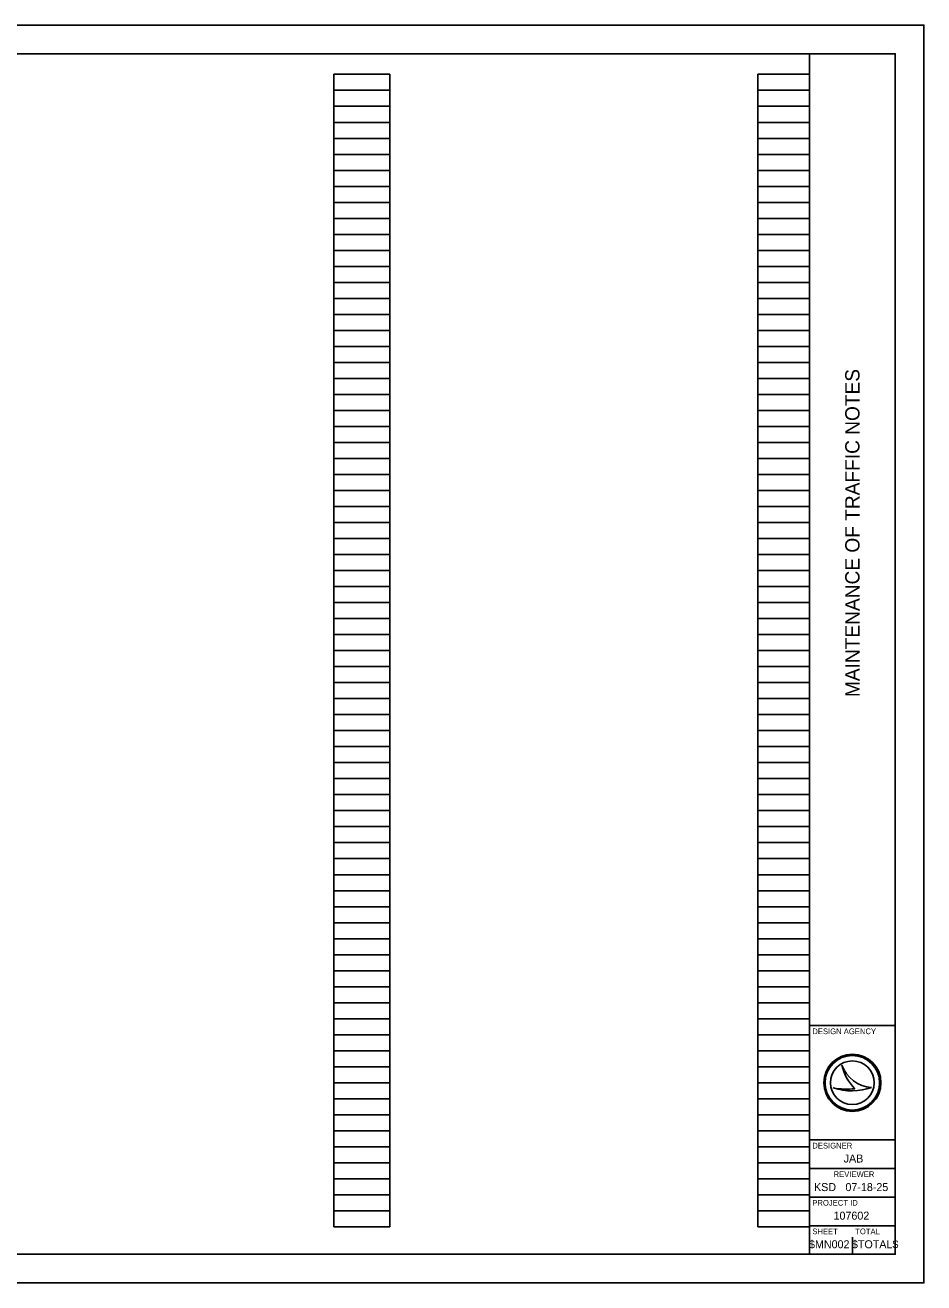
# Model space of a CAD drawing. Extents: x 0 to 34, y 0 to 22.
# Drawn here: x 18.29 to 34, y 0 to 22 of the extents above; entities that cross this region are included whole.
import ezdxf

# ---------------------------------------------------------------- set-up
doc = ezdxf.new("R2010")
doc.units = 0
for name, color, linetype in [('SH_Border', 7, 'Continuous'), ('SH_Cut_Line', 7, 'Continuous'), ('SH_Data', 7, 'Continuous')]:
    doc.layers.add(name, color=color, linetype=linetype)

msp = doc.modelspace()

# ---------------------------------------------------------------- linework, layer by layer
at = {"layer": 'SH_Border'}
for p, q in [((32, 0.5), (32, 21.5)), ((32, 4.5), (33.5, 4.5)), ((32, 2.5), (33.5, 2.5)), ((32, 2), (33.5, 2)), ((32, 1.5), (33.5, 1.5)), ((32, 1), (33.5, 1))]:
    msp.add_line(p, q, dxfattribs=at)
msp.add_lwpolyline([(1.5, 21.5), (33.5, 21.5), (33.5, 0.5), (1.5, 0.5)], close=True, dxfattribs=at)
at = {"layer": 'SH_Cut_Line'}
msp.add_lwpolyline([(0, 0), (34, 0), (34, 22), (0, 22)], close=True, dxfattribs=at)
at = {"layer": 'SH_Data'}
for p, q in [((23.68, 0.98), (23.68, 21.14)), ((23.68, 21.14), (24.66, 21.14)), ((24.66, 0.98), (24.66, 21.14)), ((31.1, 0.98), (31.1, 21.14)), ((31.1, 21.14), (32, 21.14)), ((32, 0.98), (32, 21.14)), ((23.68, 20.86), (24.66, 20.86)), ((31.1, 20.86), (32, 20.86)), ((23.68, 20.58), (24.66, 20.58)), ((31.1, 20.58), (32, 20.58)), ((23.68, 20.3), (24.66, 20.3)), ((31.1, 20.3), (32, 20.3)), ((23.68, 20.02), (24.66, 20.02)), ((31.1, 20.02), (32, 20.02)), ((23.68, 19.74), (24.66, 19.74)), ((31.1, 19.74), (32, 19.74)), ((23.68, 19.46), (24.66, 19.46)), ((31.1, 19.46), (32, 19.46)), ((23.68, 19.18), (24.66, 19.18)), ((31.1, 19.18), (32, 19.18)), ((23.68, 18.9), (24.66, 18.9)), ((31.1, 18.9), (32, 18.9)), ((23.68, 18.62), (24.66, 18.62)), ((31.1, 18.62), (32, 18.62)), ((23.68, 18.34), (24.66, 18.34)), ((31.1, 18.34), (32, 18.34)), ((23.68, 18.06), (24.66, 18.06)), ((31.1, 18.06), (32, 18.06)), ((23.68, 17.78), (24.66, 17.78)), ((31.1, 17.78), (32, 17.78)), ((23.68, 17.5), (24.66, 17.5)), ((31.1, 17.5), (32, 17.5)), ((23.68, 17.22), (24.66, 17.22)), ((31.1, 17.22), (32, 17.22)), ((23.68, 16.94), (24.66, 16.94)), ((31.1, 16.94), (32, 16.94)), ((23.68, 16.66), (24.66, 16.66)), ((31.1, 16.66), (32, 16.66)), ((23.68, 16.38), (24.66, 16.38)), ((31.1, 16.38), (32, 16.38)), ((23.68, 16.1), (24.66, 16.1)), ((31.1, 16.1), (32, 16.1)), ((23.68, 15.82), (24.66, 15.82)), ((31.1, 15.82), (32, 15.82)), ((23.68, 15.54), (24.66, 15.54)), ((31.1, 15.54), (32, 15.54)), ((23.68, 15.26), (24.66, 15.26)), ((31.1, 15.26), (32, 15.26)), ((23.68, 14.98), (24.66, 14.98)), ((31.1, 14.98), (32, 14.98)), ((23.68, 14.7), (24.66, 14.7)), ((31.1, 14.7), (32, 14.7)), ((23.68, 14.42), (24.66, 14.42)), ((31.1, 14.42), (32, 14.42)), ((23.68, 14.14), (24.66, 14.14)), ((31.1, 14.14), (32, 14.14)), ((23.68, 13.86), (24.66, 13.86)), ((31.1, 13.86), (32, 13.86)), ((23.68, 13.58), (24.66, 13.58)), ((31.1, 13.58), (32, 13.58)), ((23.68, 13.3), (24.66, 13.3)), ((31.1, 13.3), (32, 13.3)), ((23.68, 13.02), (24.66, 13.02)), ((31.1, 13.02), (32, 13.02)), ((23.68, 12.74), (24.66, 12.74)), ((31.1, 12.74), (32, 12.74)), ((23.68, 12.46), (24.66, 12.46)), ((31.1, 12.46), (32, 12.46)), ((23.68, 12.18), (24.66, 12.18)), ((31.1, 12.18), (32, 12.18)), ((23.68, 11.9), (24.66, 11.9)), ((31.1, 11.9), (32, 11.9)), ((23.68, 11.62), (24.66, 11.62)), ((31.1, 11.62), (32, 11.62)), ((23.68, 11.34), (24.66, 11.34)), ((31.1, 11.34), (32, 11.34)), ((23.68, 11.06), (24.66, 11.06)), ((31.1, 11.06), (32, 11.06)), ((23.68, 10.78), (24.66, 10.78)), ((31.1, 10.78), (32, 10.78)), ((23.68, 10.5), (24.66, 10.5)), ((31.1, 10.5), (32, 10.5)), ((23.68, 10.22), (24.66, 10.22)), ((31.1, 10.22), (32, 10.22)), ((23.68, 9.94), (24.66, 9.94)), ((31.1, 9.94), (32, 9.94)), ((23.68, 9.66), (24.66, 9.66)), ((31.1, 9.66), (32, 9.66)), ((23.68, 9.38), (24.66, 9.38)), ((31.1, 9.38), (32, 9.38)), ((23.68, 9.1), (24.66, 9.1)), ((31.1, 9.1), (32, 9.1)), ((23.68, 8.82), (24.66, 8.82)), ((31.1, 8.82), (32, 8.82)), ((23.68, 8.54), (24.66, 8.54)), ((31.1, 8.54), (32, 8.54)), ((23.68, 8.26), (24.66, 8.26)), ((31.1, 8.26), (32, 8.26)), ((23.68, 7.98), (24.66, 7.98)), ((31.1, 7.98), (32, 7.98)), ((23.68, 7.7), (24.66, 7.7)), ((31.1, 7.7), (32, 7.7)), ((23.68, 7.42), (24.66, 7.42)), ((31.1, 7.42), (32, 7.42)), ((23.68, 7.14), (24.66, 7.14)), ((31.1, 7.14), (32, 7.14)), ((23.68, 6.86), (24.66, 6.86)), ((31.1, 6.86), (32, 6.86)), ((23.68, 6.58), (24.66, 6.58)), ((31.1, 6.58), (32, 6.58)), ((23.68, 6.3), (24.66, 6.3)), ((31.1, 6.3), (32, 6.3)), ((23.68, 6.02), (24.66, 6.02)), ((31.1, 6.02), (32, 6.02)), ((23.68, 5.74), (24.66, 5.74)), ((31.1, 5.74), (32, 5.74)), ((23.68, 5.46), (24.66, 5.46)), ((31.1, 5.46), (32, 5.46)), ((23.68, 5.18), (24.66, 5.18)), ((31.1, 5.18), (32, 5.18)), ((23.68, 4.9), (24.66, 4.9)), ((31.1, 4.9), (32, 4.9)), ((23.68, 4.62), (24.66, 4.62)), ((31.1, 4.62), (32, 4.62)), ((23.68, 4.34), (24.66, 4.34)), ((31.1, 4.34), (32, 4.34)), ((23.68, 4.06), (24.66, 4.06)), ((31.1, 4.06), (32, 4.06)), ((23.68, 3.78), (24.66, 3.78)), ((31.1, 3.78), (32, 3.78)), ((32.567, 3.81), (32.567, 3.81)), ((23.68, 3.5), (24.66, 3.5)), ((31.1, 3.5), (32, 3.5)), ((32.417, 3.41), (32.417, 3.41)), ((32.75, 3.5), (32.75, 3.5)), ((33.087, 3.419), (33.087, 3.419)), ((23.68, 3.22), (24.66, 3.22)), ((31.1, 3.22), (32, 3.22)), ((23.68, 2.94), (24.66, 2.94)), ((31.1, 2.94), (32, 2.94)), ((23.68, 2.66), (24.66, 2.66)), ((31.1, 2.66), (32, 2.66)), ((23.68, 2.38), (24.66, 2.38)), ((31.1, 2.38), (32, 2.38)), ((23.68, 2.1), (24.66, 2.1)), ((31.1, 2.1), (32, 2.1)), ((23.68, 1.82), (24.66, 1.82)), ((31.1, 1.82), (32, 1.82)), ((23.68, 1.54), (24.66, 1.54)), ((31.1, 1.54), (32, 1.54)), ((23.68, 1.26), (24.66, 1.26)), ((31.1, 1.26), (32, 1.26)), ((23.68, 0.98), (24.66, 0.98)), ((31.1, 0.98), (32, 0.98)), ((32.375, 0.675), (32.375, 0.675)), ((32.75, 0.5), (32.75, 0.8))]:
    msp.add_line(p, q, dxfattribs=at)
for radius in [0.5, 0.477, 0.477, 0.382]:
    msp.add_circle((32.75, 3.5), radius, dxfattribs=at)
for centre, radius, start, end in [((33.116, 3.998), 0.58, 198.9257, 198.9319), ((33.347, 3.97), 0.796, 191.6379, 191.6421), ((33.116, 3.998), 0.58, 198.9319, 267.1657), ((33.347, 3.97), 0.796, 191.6421, 226.0947), ((32.739, 4.37), 1.013, 251.4576, 290.0832), ((32.648, 4.654), 1.266, 259.4964, 259.4995), ((32.739, 4.37), 1.013, 251.4527, 251.4576), ((32.648, 4.654), 1.266, 259.4995, 276.6672)]:
    msp.add_arc(centre, radius, start, end, dxfattribs=at)

# ---------------------------------------------------------------- texts
msp.add_text('MAINTENANCE OF TRAFFIC NOTES', height=0.25, rotation=90, dxfattribs=at).set_placement((32.875, 10.247))
for s, height, p in [('DESIGN AGENCY', 0.1, (32.05, 4.35)), ('DESIGNER', 0.1, (32.05, 2.35)), ('JAB', 0.14, (32.598, 2.105)), ('REVIEWER', 0.1, (32.422, 1.85)), ('KSD', 0.14, (32.08, 1.605)), ('07-18-25', 0.14, (32.629, 1.605)), ('PROJECT ID', 0.1, (32.05, 1.35)), ('107602', 0.14, (32.421, 1.105)), ('SHEET', 0.1, (32.05, 0.85)), ('TOTAL', 0.1, (32.8, 0.85)), ('$MN002', 0.14, (31.992, 0.605)), ('$TOTAL$', 0.14, (32.743, 0.605))]:
    msp.add_text(s, height=height, dxfattribs=at).set_placement(p)

doc.saveas('drawing.dxf')
